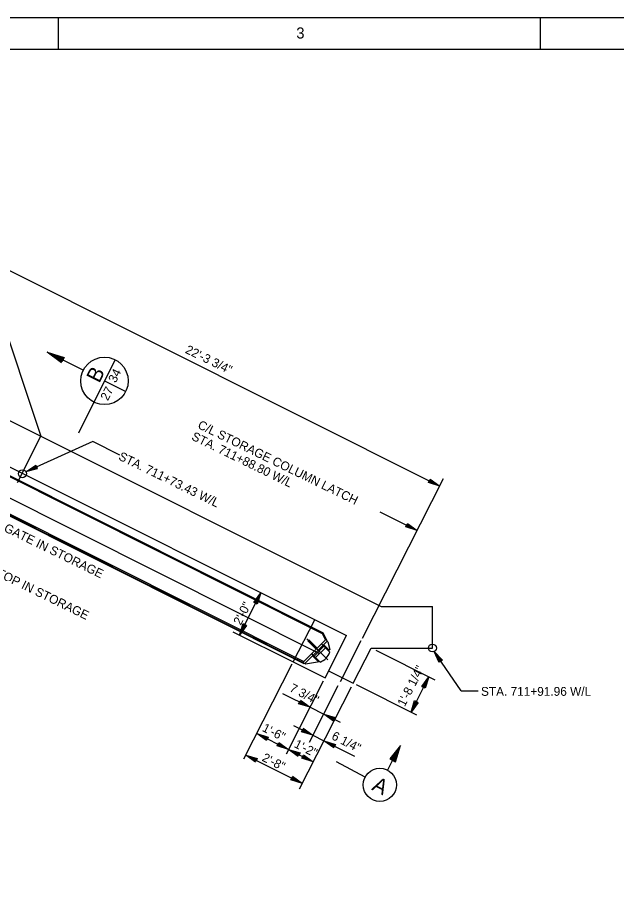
# Model space of a CAD drawing. Extents: x -48 to 108, y -5 to 100.
# Drawn here: x 43.9 to 69.16, y 38.78 to 75.96 of the extents above; entities that cross this region are included whole.
import ezdxf

# ---------------------------------------------------------------- set-up
doc = ezdxf.new("R2010")
doc.units = 0
for name, color, linetype in [('Level 1', 7, 'Continuous'), ('Level 2', 7, 'Continuous'), ('Level 22', 7, 'Continuous'), ('Level 25', 7, 'Continuous'), ('Level 3', 7, 'Continuous'), ('Level 44', 7, 'Continuous'), ('Level 50', 7, 'Continuous')]:
    doc.layers.add(name, color=color, linetype=linetype)

msp = doc.modelspace()

# ---------------------------------------------------------------- linework, layer by layer
at = {"layer": 'Level 1'}
for p, q in [((45.625, 74.625), (45.625, 75.958)), ((65.958, 74.625), (65.958, 75.958))]:
    msp.add_line(p, q, dxfattribs=at)
for points in [[(1.292, 75.958), (107.958, 75.958), (107.958, 1.292), (1.292, 1.292)], [(5.292, 74.625), (106.625, 74.625), (106.625, 2.625), (5.292, 2.625)]]:
    msp.add_lwpolyline(points, close=True, dxfattribs=at)
at = {"layer": 'Level 2'}
for p, q in [((46.667, 61.089), (45.136, 61.857)), ((47.115, 59.748), (46.461, 58.442)), ((61.399, 49.382), (61.399, 51.132))]:
    msp.add_line(p, q, dxfattribs=at)
at = {"layer": 'Level 22'}
for p, q in [((43.896, 56.36), (44.872, 58.312)), ((53.26, 49.926), (54.155, 51.715)), ((59.232, 51.132), (61.399, 51.132)), ((58.819, 49.382), (61.399, 49.382)), ((60.499, 46.679), (61.244, 48.17))]:
    msp.add_line(p, q, dxfattribs=at)
at = {"layer": 'Level 25'}
for p, q in [((41.758, 66.188), (61.714, 56.21)), ((42.83, 64.438), (44.872, 58.312)), ((45.136, 61.857), (45.136, 61.857)), ((45.322, 61.763), (45.322, 61.763)), ((39.611, 60.943), (59.232, 51.132)), ((37.718, 59.932), (57.776, 49.904)), ((39.054, 58.909), (56.783, 50.025)), ((39.107, 58.83), (56.746, 49.991)), ((37.868, 58.554), (56.603, 49.165)), ((38.382, 57.568), (56.014, 48.733)), ((38.389, 57.535), (55.975, 48.723)), ((38.477, 57.573), (55.97, 48.807)), ((58.447, 49.798), (61.875, 56.524)), ((59.186, 55.127), (60.761, 54.339)), ((55.526, 48.793), (56.434, 50.575)), ((52.977, 50.067), (55.526, 48.793)), ((56.782, 50.025), (56.747, 49.99)), ((56.747, 49.99), (56.883, 49.718)), ((56.782, 50.025), (56.957, 49.674)), ((56.868, 48.122), (57.776, 49.904)), ((56.918, 49.753), (55.935, 48.772)), ((56.957, 49.674), (56.014, 48.733)), ((56.981, 48.884), (56.104, 49.763)), ((56.981, 48.884), (56.104, 49.763)), ((56.184, 49.727), (56.14, 49.683)), ((56.493, 49.329), (56.14, 49.683)), ((56.538, 49.373), (56.184, 49.727)), ((56.825, 49.454), (56.412, 49.042)), ((56.781, 49.498), (56.722, 49.557)), ((57.075, 49.203), (56.78, 49.498)), ((57.075, 49.203), (56.808, 49.471)), ((57.046, 49.291), (56.81, 49.527)), ((57.046, 49.291), (56.81, 49.527)), ((56.987, 49.645), (56.957, 49.674)), ((56.987, 49.645), (57.075, 49.321)), ((57.516, 47.973), (58.396, 49.698)), ((56.368, 49.086), (56.309, 49.145)), ((56.662, 48.791), (56.368, 49.086)), ((56.884, 49.395), (56.471, 48.983)), ((57.075, 49.321), (57.016, 49.262)), ((57.075, 49.321), (57.016, 49.262)), ((58.063, 47.897), (58.819, 49.382)), ((59.009, 49.287), (61.502, 48.041)), ((53.446, 44.712), (55.485, 48.713)), ((55.526, 48.793), (56.868, 48.122)), ((55.726, 48.877), (55.747, 48.919)), ((55.994, 48.742), (55.975, 48.723)), ((56.043, 48.703), (56.014, 48.733)), ((56.544, 48.791), (56.043, 48.703)), ((56.574, 48.82), (56.338, 49.056)), ((56.603, 48.85), (56.544, 48.791)), ((57.019, 48.419), (58.063, 47.897)), ((55.238, 44.924), (56.802, 47.993)), ((55.795, 43.449), (57.987, 47.75)), ((56.215, 45.418), (57.426, 47.795)), ((58.176, 47.841), (60.725, 46.566)), ((55.068, 47.468), (56.237, 46.884)), ((56.237, 46.884), (56.814, 46.595)), ((56.814, 46.595), (57.503, 46.251)), ((55.532, 46.116), (56.359, 45.702)), ((53.989, 45.777), (55.331, 45.107)), ((56.359, 45.702), (56.825, 45.469)), ((56.825, 45.469), (58.109, 44.828)), ((55.331, 45.107), (56.374, 44.585)), ((53.526, 44.868), (55.911, 43.676))]:
    msp.add_line(p, q, dxfattribs=at)
msp.add_lwpolyline([(45.749, 61.411), (45.136, 61.857), (45.86, 61.632), (45.765, 61.443), (45.322, 61.763), (45.813, 61.611), (45.752, 61.489), (45.5, 61.674), (45.767, 61.59), (45.742, 61.539), (45.686, 61.581)], dxfattribs=at)
msp.add_arc((56.41, 49.457), 0.712, 290.7601, 339.1392, dxfattribs=at)
at = {"layer": 'Level 3'}
for p, q in [((48.008, 61.538), (47.115, 59.748)), ((47.561, 60.643), (48.456, 60.197)), ((59.719, 44.647), (59.5, 44.235)), ((57.338, 44.592), (58.554, 43.945))]:
    msp.add_line(p, q, dxfattribs=at)
msp.add_lwpolyline([(59.805, 44.601), (59.836, 44.585), (60.048, 45.265), (59.604, 44.709), (59.805, 44.601), (59.966, 45.107), (59.654, 44.72), (59.787, 44.649), (59.883, 44.951), (59.706, 44.729), (59.768, 44.697), (59.799, 44.793), (59.757, 44.741)], dxfattribs=at)
for centre, radius in [((47.561, 60.643), 1), ((59.183, 43.611), 0.7)]:
    msp.add_circle(centre, radius, dxfattribs=at)
at = {"layer": 'Level 44'}
for p, q in [((47.073, 58.09), (44.247, 56.806)), ((48.211, 57.512), (47.073, 58.09)), ((62.614, 47.575), (61.468, 49.23)), ((62.614, 47.575), (63.329, 47.575))]:
    msp.add_line(p, q, dxfattribs=at)
for centre in [(44.099, 56.729), (61.399, 49.382)]:
    msp.add_circle(centre, 0.167, dxfattribs=at)
at = {"layer": 'Level 50'}
for p, q in [((44.247, 56.806), (44.247, 56.806)), ((44.373, 56.863), (44.373, 56.863)), ((61.59, 56.272), (61.59, 56.272)), ((61.714, 56.21), (61.714, 56.21)), ((60.637, 54.401), (60.637, 54.401)), ((60.761, 54.339), (60.761, 54.339)), ((54.155, 51.715), (54.155, 51.715)), ((54.093, 51.591), (54.093, 51.591)), ((53.26, 49.926), (53.26, 49.926)), ((53.322, 50.05), (53.322, 50.05)), ((61.468, 49.23), (61.468, 49.23)), ((61.547, 49.116), (61.547, 49.116)), ((61.182, 48.046), (61.182, 48.046)), ((61.244, 48.17), (61.244, 48.17)), ((56.113, 46.946), (56.113, 46.946)), ((56.237, 46.884), (56.237, 46.884)), ((56.814, 46.595), (56.814, 46.595)), ((56.938, 46.533), (56.938, 46.533)), ((60.499, 46.679), (60.499, 46.679)), ((60.561, 46.803), (60.561, 46.803)), ((53.989, 45.777), (53.989, 45.777)), ((56.235, 45.764), (56.235, 45.764)), ((54.113, 45.715), (54.113, 45.715)), ((56.359, 45.702), (56.359, 45.702)), ((56.825, 45.469), (56.825, 45.469)), ((56.949, 45.407), (56.949, 45.407)), ((55.207, 45.169), (55.207, 45.169)), ((55.331, 45.107), (55.331, 45.107)), ((55.331, 45.107), (55.331, 45.107)), ((55.455, 45.045), (55.455, 45.045)), ((53.526, 44.868), (53.526, 44.868)), ((53.65, 44.806), (53.65, 44.806)), ((56.25, 44.647), (56.25, 44.647)), ((56.374, 44.585), (56.374, 44.585)), ((55.787, 43.738), (55.787, 43.738)), ((55.911, 43.676), (55.911, 43.676))]:
    msp.add_line(p, q, dxfattribs=at)
for points in [[(44.735, 56.937), (44.247, 56.806), (44.667, 57.087), (44.725, 56.959), (44.373, 56.863), (44.658, 57.054), (44.696, 56.972), (44.494, 56.918), (44.65, 57.021), (44.665, 56.987), (44.621, 56.976)], [(61.305, 56.507), (61.714, 56.21), (61.231, 56.359), (61.295, 56.485), (61.59, 56.272), (61.262, 56.373), (61.303, 56.454), (61.471, 56.331), (61.293, 56.387), (61.31, 56.421), (61.347, 56.393)], [(60.352, 54.636), (60.761, 54.339), (60.278, 54.489), (60.341, 54.615), (60.637, 54.401), (60.309, 54.503), (60.35, 54.584), (60.518, 54.461), (60.34, 54.517), (60.357, 54.551), (60.394, 54.523)], [(53.858, 51.306), (54.155, 51.715), (54.006, 51.232), (53.879, 51.295), (54.093, 51.591), (53.991, 51.263), (53.91, 51.303), (54.033, 51.471), (53.977, 51.294), (53.944, 51.31), (53.971, 51.347)], [(53.557, 50.335), (53.26, 49.926), (53.409, 50.409), (53.536, 50.345), (53.322, 50.05), (53.424, 50.378), (53.505, 50.337), (53.382, 50.169), (53.438, 50.347), (53.471, 50.33), (53.444, 50.293)], [(61.684, 48.773), (61.468, 49.23), (61.82, 48.868), (61.704, 48.787), (61.547, 49.116), (61.786, 48.87), (61.711, 48.818), (61.623, 49.007), (61.752, 48.872), (61.721, 48.851), (61.702, 48.893)], [(60.947, 47.761), (61.244, 48.17), (61.095, 47.687), (60.968, 47.75), (61.182, 48.046), (61.08, 47.718), (60.999, 47.759), (61.122, 47.927), (61.066, 47.749), (61.033, 47.766), (61.06, 47.803)], [(55.828, 47.181), (56.237, 46.884), (55.754, 47.033), (55.817, 47.16), (56.113, 46.946), (55.785, 47.047), (55.825, 47.129), (55.993, 47.006), (55.816, 47.062), (55.832, 47.095), (55.869, 47.068)], [(60.795, 47.088), (60.499, 46.679), (60.648, 47.162), (60.774, 47.099), (60.561, 46.803), (60.662, 47.131), (60.743, 47.091), (60.62, 46.923), (60.676, 47.1), (60.71, 47.084), (60.682, 47.047)], [(57.223, 46.298), (56.814, 46.595), (57.297, 46.446), (57.234, 46.32), (56.938, 46.533), (57.266, 46.432), (57.226, 46.351), (57.058, 46.474), (57.235, 46.418), (57.219, 46.384), (57.182, 46.412)], [(54.398, 45.48), (53.989, 45.777), (54.472, 45.628), (54.409, 45.502), (54.113, 45.715), (54.441, 45.614), (54.401, 45.533), (54.232, 45.656), (54.41, 45.6), (54.393, 45.566), (54.356, 45.594)], [(55.95, 45.999), (56.359, 45.702), (55.876, 45.851), (55.94, 45.978), (56.235, 45.764), (55.907, 45.866), (55.948, 45.947), (56.116, 45.824), (55.938, 45.88), (55.955, 45.913), (55.992, 45.886)], [(54.922, 45.404), (55.331, 45.107), (54.848, 45.256), (54.911, 45.382), (55.207, 45.169), (54.879, 45.27), (54.919, 45.351), (55.088, 45.228), (54.91, 45.284), (54.927, 45.318), (54.963, 45.29)], [(57.234, 45.173), (56.825, 45.469), (57.308, 45.32), (57.245, 45.194), (56.949, 45.407), (57.277, 45.306), (57.237, 45.225), (57.068, 45.348), (57.246, 45.292), (57.229, 45.258), (57.193, 45.286)], [(55.74, 44.81), (55.331, 45.107), (55.814, 44.957), (55.751, 44.831), (55.455, 45.045), (55.783, 44.943), (55.742, 44.862), (55.574, 44.985), (55.752, 44.929), (55.735, 44.895), (55.698, 44.923)], [(53.935, 44.571), (53.526, 44.868), (54.009, 44.719), (53.946, 44.593), (53.65, 44.806), (53.978, 44.705), (53.937, 44.624), (53.769, 44.746), (53.947, 44.69), (53.93, 44.657), (53.893, 44.684)], [(55.965, 44.882), (56.374, 44.585), (55.891, 44.734), (55.955, 44.86), (56.25, 44.647), (55.922, 44.748), (55.963, 44.829), (56.131, 44.706), (55.953, 44.762), (55.97, 44.796), (56.007, 44.768)], [(55.502, 43.972), (55.911, 43.676), (55.428, 43.825), (55.491, 43.951), (55.787, 43.738), (55.459, 43.839), (55.499, 43.92), (55.668, 43.797), (55.49, 43.853), (55.507, 43.887), (55.544, 43.859)]]:
    msp.add_lwpolyline(points, dxfattribs=at)

# ---------------------------------------------------------------- texts
at = {"layer": 'Level 1'}
msp.add_text('3', height=0.467, dxfattribs=at).set_placement((55.656, 75.077))
at = {"layer": 'Level 25'}
for s, height, rotation, p in [('22\'-3 3/4"', 0.3733, 334, (50.941, 61.837)), ('C/L STORAGE COLUMN LATCH', 0.37333, 334, (51.462, 58.666)), ('STA. 711+88.80 W/L', 0.37333, 334, (51.202, 58.179)), ('STA. 711+73.43 W/L', 0.37333, 334, (48.121, 57.338)), ('GATE IN STORAGE', 0.37333, 334, (43.287, 54.318)), ('GATE STOP IN STORAGE', 0.37333, 334, (41.329, 53.223)), ('2\'-0"', 0.3733, 63, (53.311, 50.316)), ("1'-8 1/4''", 0.3733, 63, (60.233, 46.884)), ('7 3/4"', 0.3733, 333, (55.339, 47.574)), ('1\'-6"', 0.3733, 333, (54.187, 45.896)), ('6 1/4"', 0.3733, 333, (57.113, 45.554)), ('1\'-2"', 0.3733, 333, (55.535, 45.215)), ('2\'-8"', 0.3733, 333, (54.178, 44.644)), ('A', 0.64, 333, (58.806, 43.421))]:
    msp.add_text(s, height=height, rotation=rotation, dxfattribs=at).set_placement(p)
msp.add_text('STA. 711+91.96 W/L', height=0.37333, dxfattribs=at).set_placement((63.45, 47.366))
at = {"layer": 'Level 3'}
for s, height, p in [('B', 0.64, (47.341, 60.521)), ('34', 0.3743, (48.035, 60.535)), ('27', 0.3743, (47.704, 59.781))]:
    msp.add_text(s, height=height, rotation=63.5, dxfattribs=at).set_placement(p)

doc.saveas('drawing.dxf')
